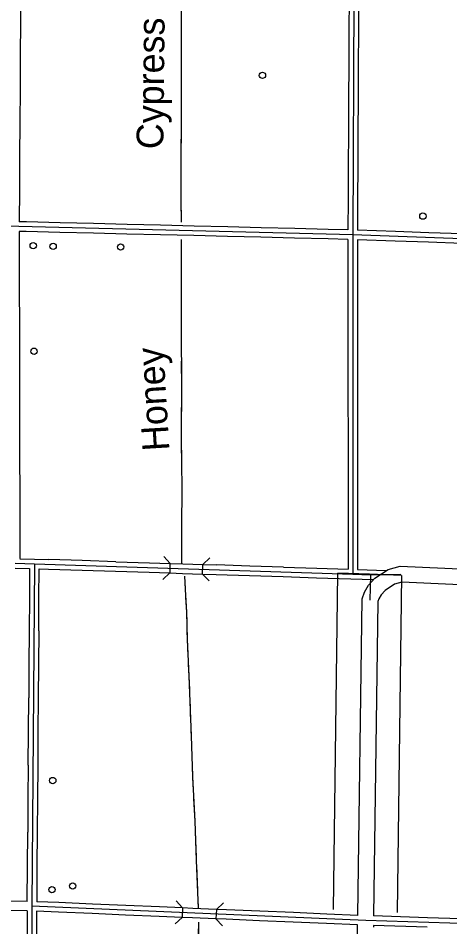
# Model space of a CAD drawing. Extents: x -4306 to 3843, y 131 to 8341.
# Drawn here: x -274 to 814, y 4435 to 6723 of the extents above; entities that cross this region are included whole.
import ezdxf

# ---------------------------------------------------------------- set-up
doc = ezdxf.new("R2010")
doc.units = 0
for name, color, linetype in [('10', 7, 'Continuous'), ('31', 7, 'Continuous'), ('32', 7, 'Continuous'), ('38', 7, 'Continuous'), ('53', 7, 'Continuous'), ('56', 7, 'Continuous'), ('57', 7, 'Continuous')]:
    doc.layers.add(name, color=color, linetype=linetype)

msp = doc.modelspace()

# ---------------------------------------------------------------- linework, layer by layer
at = {"layer": '10'}
for points in [[(581.8, 4463.7), (592.6, 5261.1), (598.4, 5277.4), (608.7, 5295.2), (624.9, 5312.8), (658.1, 5334.6), (688.3, 5342.8), (970.2, 5330.2)], [(968.7, 5290.2), (692.8, 5302.6), (674.8, 5297.7), (651, 5282.1), (641.1, 5271.4), (634.9, 5260.6), (632.5, 5254), (621.8, 4462.2)], [(577.7, 4058.2), (580.3, 4349.6), (581.5, 4439.7)], [(621.5, 4438.2), (621.4, 4434.2)]]:
    msp.add_lwpolyline(points, dxfattribs=at)
at = {"layer": '31'}
for p, q in [((-269.5, 5362), (-232.4, 5361)), ((-232.4, 5361), (-196.6, 5359.9)), ((-281.8, 5338.4), (-244.9, 5337.3)), ((-220.9, 5336.6), (-197.4, 5335.9)), ((-27.7, 5354.4), (56.7, 5351.7)), ((56.7, 5351.7), (109.5, 5350)), ((108.8, 5326.1), (109.5, 5350.1)), ((109.5, 5350), (141.2, 5349)), ((141.2, 5349), (191.7, 5347.4)), ((190.7, 5323.4), (191.5, 5347.4)), ((191.7, 5347.4), (225.6, 5346.3)), ((394.5, 5340.9), (479, 5338.1)), ((479, 5338.1), (557.4, 5335.6)), ((581.4, 5334.9), (653.8, 5332.5)), ((-28.5, 5330.4), (56, 5327.7)), ((56, 5327.7), (108.5, 5326)), ((108.5, 5326), (140.4, 5325)), ((140.4, 5325), (190.9, 5323.4)), ((190.9, 5323.4), (224.9, 5322.3)), ((393.7, 5316.9), (478.2, 5314.2)), ((478.2, 5314.2), (621.8, 5309.5)), ((-246.1, 5180.1), (-246.7, 5095.6)), ((-222.1, 5179.9), (-222.7, 5095.5)), ((-246.7, 5095.6), (-247.3, 5011.2)), ((-222.7, 5095.5), (-223.3, 5011)), ((-248.6, 4842.2), (-249.2, 4757.7)), ((-224.6, 4842), (-225.2, 4757.5)), ((-249.2, 4757.7), (-249.9, 4673.2)), ((-225.2, 4757.5), (-225.9, 4673)), ((-251.3, 4474.7), (-251.4, 4402.1)), ((-227.3, 4474), (-227.4, 4402))]:
    msp.add_line(p, q, dxfattribs=at)
for points in [[(-112.2, 5357.1), (-196.6, 5359.9)], [(-27.7, 5354.4), (-112.2, 5357.1)], [(-244.9, 5337.3), (-245.4, 5264.6)], [(-221.4, 5264.4), (-220.9, 5336.6)], [(-197.4, 5335.9), (-112.9, 5333.2)], [(-112.9, 5333.2), (-28.5, 5330.4)], [(310.1, 5343.6), (225.6, 5346.3)], [(394.5, 5340.9), (310.1, 5343.6)], [(224.9, 5322.3), (309.3, 5319.6)], [(309.3, 5319.6), (393.7, 5316.9)], [(-245.4, 5264.6), (-246.1, 5180.1)], [(-222.1, 5179.9), (-221.4, 5264.4)], [(-248, 4926.7), (-247.3, 5011.2)], [(-223.3, 5011), (-224, 4926.5)], [(-248.6, 4842.2), (-248, 4926.7)], [(-224, 4926.5), (-224.6, 4842)], [(-250.5, 4588.7), (-249.9, 4673.2)], [(-225.9, 4673), (-226.5, 4588.5)], [(-251.2, 4498.7), (-250.5, 4588.7)], [(-226.5, 4588.5), (-227.2, 4498)]]:
    msp.add_lwpolyline(points, dxfattribs=at)
at = {"layer": '32'}
for p, q in [((573.1, 7028.1), (569.1, 6177.8)), ((-267.5, 6798.5), (-268, 6714)), ((559.9, 6774.7), (559.5, 6690.2)), ((583.9, 6774.6), (583.5, 6690.1)), ((-268, 6714), (-268.6, 6629.5)), ((559.5, 6690.2), (559.1, 6605.7)), ((583.5, 6690.1), (583.1, 6605.6)), ((-268.6, 6629.5), (-269.2, 6545)), ((559.1, 6605.7), (558.7, 6521.2)), ((583.1, 6605.6), (582.7, 6521.1)), ((-269.2, 6545), (-269.7, 6460.5)), ((558.7, 6521.2), (558.3, 6436.7)), ((582.7, 6521.1), (582.3, 6436.6)), ((-269.7, 6460.5), (-270.3, 6376)), ((558.3, 6436.7), (557.9, 6352.2)), ((582.3, 6436.6), (581.9, 6352.1)), ((-270.3, 6376), (-270.9, 6291.6)), ((557.9, 6352.2), (557.5, 6267.8)), ((581.9, 6352.1), (581.5, 6267.6)), ((-270.9, 6291.6), (-271.4, 6210.6)), ((557.5, 6267.8), (557.1, 6190.1)), ((581.5, 6267.6), (581.1, 6189.4)), ((-271.9, 6198.6), (-1756.9, 6213.2)), ((-252.7, 6210.1), (-271.6, 6210.6)), ((-168.2, 6208), (-252.7, 6210.1)), ((-83.8, 6205.9), (-168.2, 6208)), ((0.7, 6203.8), (-83.8, 6205.9)), ((85.2, 6201.7), (0.7, 6203.8)), ((569.1, 6177.8), (-271.9, 6198.6)), ((-271.5, 6186.5), (-271.3, 6122.7)), ((-253.3, 6186.1), (-271.5, 6186.5)), ((-168.8, 6184), (-253.3, 6186.1)), ((-84.4, 6181.9), (-168.8, 6184)), ((0.1, 6179.8), (-84.4, 6181.9)), ((84.6, 6177.7), (0.1, 6179.8)), ((169.6, 6199.7), (85.2, 6201.7)), ((254.1, 6197.6), (169.6, 6199.7)), ((338.6, 6195.5), (254.1, 6197.6)), ((423, 6193.4), (338.6, 6195.5)), ((507.5, 6191.3), (423, 6193.4)), ((557.1, 6190.1), (507.5, 6191.3)), ((676.5, 6186), (581.1, 6189.4)), ((760.9, 6183), (676.5, 6186)), ((845.4, 6180), (760.9, 6183)), ((169, 6175.7), (84.6, 6177.7)), ((253.5, 6173.6), (169, 6175.7)), ((338, 6171.5), (253.5, 6173.6)), ((422.4, 6169.4), (338, 6171.5)), ((506.9, 6167.3), (422.4, 6169.4)), ((557.1, 6166.1), (506.9, 6167.3)), ((557.1, 6166.1), (557.1, 6098.7)), ((569.1, 6177.8), (569.4, 5323.2)), ((2280.4, 6116.9), (569.1, 6177.8)), ((581.1, 6165.3), (581.1, 6098.7)), ((675.7, 6162), (581.1, 6165.3)), ((760.1, 6159), (675.7, 6162)), ((844.5, 6156), (760.1, 6159)), ((-271.3, 6122.7), (-271.1, 6038.2)), ((557.1, 6098.7), (557.1, 6014.2)), ((581.1, 6098.7), (581.1, 6014.2)), ((-271.1, 6038.2), (-270.9, 5953.7)), ((557.1, 6014.2), (557.2, 5929.7)), ((581.1, 6014.2), (581.2, 5929.7)), ((-270.9, 5953.7), (-270.7, 5869.2)), ((557.2, 5929.7), (557.2, 5845.2)), ((581.2, 5929.7), (581.2, 5845.3)), ((-270.7, 5869.2), (-270.5, 5784.7)), ((557.2, 5845.2), (557.2, 5760.8)), ((581.2, 5845.3), (581.3, 5760.8)), ((-270.5, 5784.7), (-270.3, 5700.2)), ((557.2, 5760.8), (557.3, 5676.3)), ((581.3, 5760.8), (581.3, 5676.3)), ((-270.3, 5700.2), (-270.1, 5615.8)), ((557.3, 5676.3), (557.3, 5591.8)), ((581.3, 5676.3), (581.3, 5591.8)), ((-270.1, 5615.8), (-269.9, 5531.3)), ((557.3, 5591.8), (557.4, 5507.3)), ((581.3, 5591.8), (581.4, 5507.3)), ((-269.9, 5531.3), (-269.7, 5446.8)), ((557.4, 5507.3), (557.4, 5422.8)), ((581.4, 5507.3), (581.4, 5422.8)), ((-269.7, 5446.8), (-269.5, 5362.3)), ((557.4, 5422.8), (557.4, 5335.6)), ((581.4, 5422.8), (581.4, 5334.9)), ((-281.4, 5350.4), (-232.8, 5349)), ((-232.8, 5349), (-239.3, 4486.5)), ((-232.8, 5349), (569.4, 5323.2)), ((569.4, 5323.2), (613.9, 5321.6)), ((613.9, 5321.6), (612.6, 5257.5)), ((613.9, 5321.6), (690.6, 5322.7)), ((-251.2, 4498.7), (-340.4, 4499.7)), ((-239.3, 4486.5), (-240, 4096.4)), ((602.5, 4450.9), (-239.3, 4486.5)), ((-171.2, 4495.7), (-227.2, 4498)), ((-86.7, 4492.1), (-171.2, 4495.7)), ((-2.3, 4488.5), (-86.7, 4492.1)), ((82.1, 4484.9), (-2.3, 4488.5)), ((-251.3, 4474.7), (-340.7, 4475.7)), ((-172.2, 4471.7), (-227.3, 4474)), ((-87.8, 4468.1), (-172.2, 4471.7)), ((-3.3, 4464.5), (-87.8, 4468.1)), ((81.1, 4460.9), (-3.3, 4464.5)), ((140.2, 4482.5), (82.1, 4484.9)), ((140.2, 4482.5), (139.1, 4458.5)), ((166.5, 4481.3), (140.2, 4482.5)), ((225.5, 4478.8), (166.5, 4481.3)), ((225.5, 4478.8), (224.5, 4454.9)), ((250.9, 4477.8), (225.5, 4478.8)), ((335.3, 4474.2), (250.9, 4477.8)), ((419.7, 4470.6), (335.3, 4474.2)), ((504.2, 4467), (419.7, 4470.6)), ((581.8, 4463.7), (504.2, 4467)), ((139.1, 4458.5), (81.1, 4460.9)), ((165.5, 4457.4), (139.1, 4458.5)), ((224.5, 4454.9), (165.5, 4457.4)), ((249.9, 4453.8), (224.5, 4454.9)), ((334.3, 4450.2), (249.9, 4453.8)), ((418.7, 4446.6), (334.3, 4450.2)), ((503.1, 4443.1), (418.7, 4446.6)), ((581.5, 4439.7), (503.1, 4443.1)), ((1130.8, 4433), (602.5, 4450.9)), ((757.3, 4457.6), (621.8, 4462.2)), ((841.8, 4454.8), (757.3, 4457.6)), ((756.5, 4433.6), (621.5, 4438.2))]:
    msp.add_line(p, q, dxfattribs=at)
at = {"layer": '38'}
for points in [[(92.9, 5367.5), (109.3, 5350)], [(191.7, 5347.4), (209.2, 5363.8)], [(108.5, 5326), (91, 5309.6)], [(207.3, 5305.9), (190.9, 5323.4)], [(124, 4500.1), (140.2, 4482.5)], [(225.5, 4478.8), (243.2, 4495.1)], [(139.2, 4458.5), (121.5, 4442.2)], [(240.7, 4437.2), (224.5, 4454.9)]]:
    msp.add_lwpolyline(points, dxfattribs=at)
at = {"layer": '53'}
for p, q in [((521.1, 4478.6), (532, 5325.5)), ((611.3, 5322.8), (532, 5325.5)), ((691.9, 5319.8), (611.3, 5322.8)), ((691.9, 5319.8), (680.9, 4470.6))]:
    msp.add_line(p, q, dxfattribs=at)
at = {"layer": '56'}
for points in [[(137, 7010.5), (136.7, 6978.4), (137.2, 6875.4), (136.8, 6800.3), (136.9, 6727.5), (136.9, 6612.5), (136.7, 6457.1), (136.1, 6359.3), (136, 6263.3), (137.2, 6210)], [(136.9, 6704.2), (136.9, 6640.8)], [(136.9, 6619.7), (136.9, 6612.5), (136.8, 6556.3)], [(136.8, 6535.2), (136.7, 6503.5)], [(136.7, 6503.5), (136.7, 6471.8)], [(136.6, 6450.7), (136.2, 6387.4)], [(136.1, 6366.2), (136.1, 6359.3), (136, 6302.9)], [(136, 6281.7), (136, 6263.3), (137, 6218.4)], [(137.2, 6166.1), (137.1, 6057.3), (136.7, 5955.8), (137.5, 5782.3), (136.8, 5681.7), (137.5, 5591.2), (138.2, 5550.4), (138, 5431.7), (137.9, 5349.1)], [(137.2, 6166.1), (137.1, 6134.5)], [(137.1, 6113.3), (137.1, 6057.3), (137, 6050)], [(137, 6028.8), (136.8, 5965.5)], [(136.8, 5944.4), (137.1, 5881)], [(137.2, 5859.9), (137.5, 5796.5)], [(137.5, 5775.4), (137, 5712)], [(136.9, 5690.9), (136.8, 5681.7), (137, 5659.2)], [(137, 5659.2), (137.2, 5627.5)], [(137.3, 5606.4), (137.5, 5591.2), (138.2, 5550.4), (138.2, 5543)], [(138.2, 5521.9), (138.1, 5458.6)], [(138, 5437.4), (138, 5431.7), (137.9, 5374.1)], [(145, 5317.6), (147, 5284.2), (150.3, 5227.5), (151.6, 5159.7), (156.3, 5066.2), (161.9, 4915.7), (165.2, 4812.6), (170.9, 4701), (174.9, 4602.5), (179.8, 4480.8)], [(145, 5317.6), (146.9, 5285.9)], [(148.1, 5264.9), (150.3, 5227.5), (150.8, 5201.6)], [(151.2, 5180.4), (151.6, 5159.7), (153.7, 5117.1)], [(154.8, 5096), (156.3, 5066.2), (157.6, 5032.7)], [(158.3, 5011.6), (160.7, 4948.3)], [(161.5, 4927.2), (161.9, 4915.7), (163.6, 4863.9)], [(164.3, 4842.7), (165.2, 4812.6), (165.3, 4811.1)], [(165.3, 4811.1), (166.9, 4779.4)], [(168, 4758.3), (170.9, 4701), (171.1, 4695.1)], [(172, 4673.9), (174.6, 4610.6)], [(175.4, 4589.5), (178, 4526.2)], [(178.8, 4505.1), (179.8, 4480.8)], [(180.3, 4446.2), (177.7, 4261), (176.6, 4135.8), (176.6, 4109.4)], [(180.3, 4446.2), (179.8, 4414.5)]]:
    msp.add_lwpolyline(points, dxfattribs=at)
at = {"layer": '57'}
for centre in [(341.6, 6579.4), (745.9, 6224.9), (-236, 6150.4), (-185.7, 6148.8), (-15.6, 6147.2), (-233.9, 5884.5), (-186.7, 4803.3), (-188.7, 4528.5), (-136.4, 4537.8)]:
    msp.add_circle(centre, 8, dxfattribs=at)

# ---------------------------------------------------------------- texts
at = {"layer": '56'}
for s, rotation, p in [('Cypress', 89.4245, (91.9, 6393.2)), ('Honey', 93.4261, (107.4, 5635))]:
    msp.add_text(s, height=67.59, rotation=rotation, dxfattribs=at).set_placement(p)

doc.saveas('drawing.dxf')
